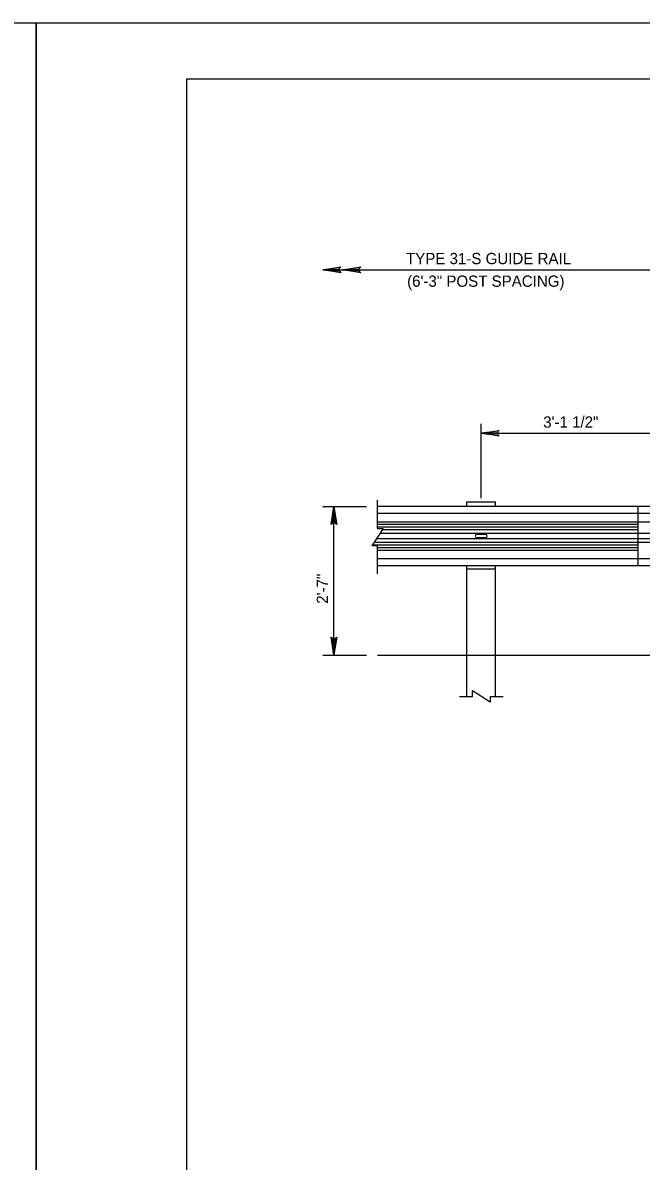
# Model space of a CAD drawing. Extents: x 637628 to 640188, y 298266 to 300751.
# Drawn here: x 639116 to 639280.6, y 299150.6 to 299453.6 of the extents above; entities that cross this region are included whole.
import ezdxf

# ---------------------------------------------------------------- set-up
doc = ezdxf.new("R2010")
doc.units = 0
for name, color, linetype in [('1', 7, 'Continuous'), ('2', 7, 'Continuous'), ('PLT-BNDY', 7, 'Continuous'), ('S-ABUT-CONC', 7, 'Continuous'), ('S-ANNO-CELL', 7, 'Continuous')]:
    doc.layers.add(name, color=color, linetype=linetype)

msp = doc.modelspace()

# ---------------------------------------------------------------- linework, layer by layer
at = {"layer": '1'}
msp.add_line((639279.71, 299309.11), (639279.71, 299324.84), dxfattribs=at)
msp.add_lwpolyline([(639945.52, 298874.58), (639945.52, 299438.55), (639159.55, 299438.55), (639159.55, 298874.58), (639945.52, 298874.58), (639945.52, 298900.93), (639745.53, 298900.93), (639745.53, 298965.61), (639945.52, 298965.61), (639945.52, 298994.57), (639745.53, 298994.57), (639745.53, 298874.58), (639824.33, 298874.58), (639824.33, 298900.93), (639824.33, 298874.58), (639901.33, 298874.58), (639901.33, 298900.93), (639901.33, 298888.62), (639945.52, 298888.62)], dxfattribs=at)
at = {"layer": '2'}
for p, q in [((639234.18, 299326.12), (639241.82, 299326.12)), ((639234.18, 299308.27), (639241.82, 299308.27)), ((639210.37, 299285.33), (639241.82, 299285.33))]:
    msp.add_line(p, q, dxfattribs=at)
for points in [[(639200.41, 299387.27), (639200.24, 299387.6), (639195.87, 299387.84), (639200.41, 299387.27), (639200.64, 299387.07), (639195.87, 299387.84), (639200.24, 299388.05), (639200.4, 299388.38), (639195.87, 299387.84), (639200.64, 299388.6), (639200.4, 299388.38)], [(639205.7, 299387.27), (639205.53, 299387.6), (639201.16, 299387.84), (639205.7, 299387.27), (639205.93, 299387.07), (639201.16, 299387.84), (639205.53, 299388.05), (639205.69, 299388.38), (639201.16, 299387.84), (639205.93, 299388.6), (639205.69, 299388.38)], [(639242.54, 299343.76), (639242.37, 299344.09), (639238, 299344.33), (639242.54, 299343.76), (639242.78, 299343.56), (639238, 299344.33), (639242.37, 299344.55), (639242.53, 299344.87), (639238, 299344.33), (639242.78, 299345.09), (639242.53, 299344.87)], [(639198.23, 299320.31), (639198.56, 299320.47), (639198.8, 299324.84), (639198.23, 299320.31), (639198.03, 299320.07), (639198.8, 299324.84), (639199.02, 299320.48), (639199.34, 299320.32), (639198.8, 299324.84), (639199.56, 299320.07), (639199.34, 299320.32)], [(639199.37, 299289.87), (639199.04, 299289.7), (639198.8, 299285.33), (639199.37, 299289.87), (639199.57, 299290.1), (639198.8, 299285.33), (639198.58, 299289.69), (639198.26, 299289.85), (639198.8, 299285.33), (639198.04, 299290.1), (639198.26, 299289.85)]]:
    msp.add_lwpolyline(points, dxfattribs=at)
at = {"layer": 'PLT-BNDY'}
for points in [[(638278.52, 299453.58), (639119.52, 299453.58), (639119.52, 298859.58), (638278.52, 298859.58)], [(639119.52, 299453.58), (639960.52, 299453.58), (639960.52, 298859.58), (639119.52, 298859.58)]]:
    msp.add_lwpolyline(points, close=True, dxfattribs=at)
at = {"layer": 'S-ABUT-CONC'}
for p, q in [((639195.87, 299387.84), (639287.66, 299387.84)), ((639238, 299327.1), (639238, 299346.82)), ((639238, 299344.33), (639287.66, 299344.33)), ((639195.87, 299324.84), (639207.44, 299324.84)), ((639198.8, 299285.33), (639198.8, 299324.84)), ((639195.87, 299285.33), (639207.44, 299285.33))]:
    msp.add_line(p, q, dxfattribs=at)
at = {"layer": 'S-ANNO-CELL'}
for p, q in [((639210.37, 299319.03), (639210.37, 299326.53)), ((639234.18, 299324.84), (639234.18, 299326.12)), ((639241.82, 299324.84), (639241.82, 299326.12)), ((639279.71, 299324.84), (639210.37, 299324.84)), ((639279.71, 299322.99), (639210.37, 299322.99)), ((639295.62, 299324.84), (639279.71, 299324.84)), ((639295.62, 299322.99), (639279.71, 299322.99)), ((639279.71, 299320.73), (639210.37, 299320.73)), ((639279.71, 299320.05), (639210.37, 299320.05)), ((639295.62, 299320.73), (639279.71, 299320.73)), ((639211.87, 299319.03), (639208.87, 299314.4)), ((639279.71, 299319.36), (639210.37, 299319.36)), ((639210.37, 299319.03), (639211.87, 299319.03)), ((639279.71, 299317.68), (639210.99, 299317.68)), ((639279.71, 299318.67), (639211.64, 299318.67)), ((639238, 299317.45), (639236.89, 299317.45)), ((639239.12, 299317.45), (639238, 299317.45)), ((639295.62, 299317.68), (639279.71, 299317.68)), ((639210.37, 299314.4), (639208.87, 299314.4)), ((639279.71, 299314.6), (639209, 299314.6)), ((639279.71, 299315.28), (639209.44, 299315.28)), ((639279.71, 299316.27), (639210.09, 299316.27)), ((639210.37, 299306.9), (639210.37, 299314.4)), ((639279.71, 299313.86), (639210.37, 299313.86)), ((639238, 299316.5), (639236.89, 299316.5)), ((639239.12, 299316.5), (639238, 299316.5)), ((639295.62, 299316.27), (639279.71, 299316.27)), ((639295.62, 299315.28), (639279.71, 299315.28)), ((639279.71, 299313.18), (639210.37, 299313.18)), ((639279.71, 299310.96), (639210.37, 299310.96)), ((639295.62, 299310.96), (639279.71, 299310.96)), ((639279.71, 299309.11), (639210.37, 299309.11)), ((639234.18, 299285.33), (639234.18, 299309.11)), ((639241.82, 299285.33), (639241.82, 299309.11)), ((639295.62, 299309.11), (639279.71, 299309.11)), ((639234.18, 299274.31), (639234.18, 299285.33)), ((639238, 299285.33), (639581.11, 299285.33)), ((639241.82, 299274.31), (639241.82, 299285.33)), ((639235.68, 299274.31), (639235.68, 299275.81)), ((639240.32, 299272.81), (639235.68, 299275.81)), ((639232.18, 299274.31), (639235.68, 299274.31)), ((639240.32, 299274.31), (639240.32, 299272.81)), ((639240.32, 299274.31), (639243.82, 299274.31))]:
    msp.add_line(p, q, dxfattribs=at)
for centre, start, end in [((639236.89, 299316.97), 90, 270), ((639239.12, 299316.97), 270, 90)]:
    msp.add_arc(centre, 0.478, start, end, dxfattribs=at)

# ---------------------------------------------------------------- texts
at = {"layer": 'S-ABUT-CONC'}
for s, p in [('TYPE 31-S GUIDE RAIL', (639217.97, 299389.34)), ('(6\'-3" POST SPACING)', (639218.27, 299383.32)), ('3\'-1 1/2"', (639254.48, 299345.83))]:
    msp.add_text(s, height=3, dxfattribs=at).set_placement(p)
msp.add_text('2\'-7"', height=3, rotation=90, dxfattribs=at).set_placement((639197.19, 299298.98))

doc.saveas('drawing.dxf')
